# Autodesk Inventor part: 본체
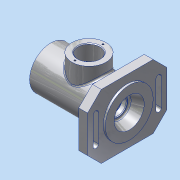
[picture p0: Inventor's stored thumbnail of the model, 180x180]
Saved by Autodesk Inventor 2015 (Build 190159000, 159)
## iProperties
Created: 2017-10
Part Number: 본체
Material: 알루미늄 6061
Document SubType Name: Modeling
Designer: Administrator
Density: 2.7 g/cm^3
Appearance: 알루미늄 - 평지
Mass: 781.743 g
Surface Area: 663.75 cm^2
Volume: 289.534 cm^3
Author: Administrator
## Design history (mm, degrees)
sketch "스케치1"
  geometry: C1 r 31 at (0, 0); 1 further point
  constraints: 1 centre point, 1 coincident
  dimensions: "d1" = 62 diameter of C1
extrude "돌출1" new body sketch "스케치1" stored distance "d2" = 99; taper "d3" = 0 deg
sketch "스케치2"
  geometry: L1 (-58, 47)-(58, 47); L2 (58, 47)-(58, -47); L3 (58, -47)-(-58, -47); L4 (-58, -47)-(-58, 47); 3 further points
  constraints: 8 end point, 2 midpoint, 2 parallel, 1 horizontal, 1 horizontal alignment, 1 perpendicular, 1 vertical alignment
  dimensions: "d4" = 116 distance between parallel lines of L2 L4; "d5" = 94 distance between parallel lines of L3 L1
extrude "돌출2" join sketch "스케치2" distance "d6" = 13; taper "d7" = 0 deg
chamfer "모따기1" distance "d8" = 20; stored, may be unused: second distance "d9" = 2, angle "d10" = 45 deg
sketch "스케치3"
  geometry: L1 (-46, 20)-(-46, -20); L2 (-50, 20)-(-50, -20); L3 (-42, -20)-(-42, 20); L4 (46, 20)-(46, -20); L5 (42, 20)-(42, -20); L6 (50, -20)-(50, 20); A1 r 4 centre (-46, 20) between (-42, 20) and (-50, 20); A2 r 4 centre (-46, -20) between (-50, -20) and (-42, -20); A3 r 4 centre (46, 20) between (50, 20) and (42, 20); A4 r 4 centre (46, -20) between (42, -20) and (50, -20); 3 further points
  constraints: 16 end point, 8 point on circle, 8 tangent, 4 centre point, 3 parallel, 2 horizontal alignment, 2 midpoint, 1 vertical
  dimensions: "d11" = 40 distance of L1.end L1.start; "d12" = 4 radius of A1; "d13" = 46 horizontal distance of point (0, 0) L1.end; "d14" = 4 radius of A3; "d15" = 92 distance of L4.end L1.end; "d16" = 40 distance of L4.end L4.start
extrude "돌출3" cut sketch "스케치3" stored distance "d17" = 13; taper "d18" = 0 deg
sketch "스케치4"
  geometry: C1 r 35 at (0, 0); 1 further point
  constraints: 1 centre point, 1 coincident
  dimensions: "d19" = 70 diameter of C1
extrude "돌출4" join sketch "스케치4" distance "d20" = 3; taper "d21" = 0 deg
sketch "스케치5"
  geometry: L1 (31, 49.5)-(-31, 49.5) reference; L2 (0, 49.5)-(0, -65.634); L3 (0, 49.5)-(21, 49.5); L4 (21, 49.5)-(21, 40.5); L5 (21, 40.5)-(24, 40.5); L6 (24, 40.5)-(24, 37.5); L7 (24, 37.5)-(21, 37.5); L8 (21, 37.5)-(21, 30.458); L9 (21, 30.458)-(17.5, 30.458); L10 (17.5, 30.458)-(17.5, 27.208); L11 (17.5, 27.208)-(18.5, 27.208); L12 (18.5, 27.208)-(18.5, 25.458); L13 (18.5, 25.458)-(17.5, 25.458); L14 (17.5, 25.458)-(17.5, 14.458); L15 (17.5, 14.458)-(0, 14.458); 1 further point
  constraints: 28 end point, 7 perpendicular, 4 vertical, 2 horizontal, 2 point on line, 1 midpoint
  dimensions: "d22" = 42 diameter of L4 L2; "d23" = 9 distance of L3.end L4.end; "d24" = 3 distance of L5.end L6.end; "d25" = 48 diameter of L6 L2; "d26" = 42 diameter of L8 L2; "d27" = 35 diameter of L10 L2; "d28" = 3.25 distance of L9.end L10.end; "d29" = 37 diameter of L12 L2; "d30" = 1.75 distance of L11.end L12.end; "d31" = 35 diameter of L14 L2; "d32" = 19.04189 distance between parallel lines of L9 L3; "d33" = 11 distance of L13.end L14.end
revolve "회전1" sketch "스케치5" stored, may be unused: angle "d34" = 90 deg
sketch "스케치6"
  geometry: L1 (0, 14.458)-(0, -65.5); L2 (0, 14.458)-(26, 14.458); L3 (17.5, 14.458)-(-17.5, 14.458) reference; L4 (26, 14.458)-(26, -23.542); L5 (26, -23.542)-(18.5, -23.542); L6 (18.5, -23.542)-(18.5, -34.542); L7 (18.5, -34.542)-(16.5, -34.542); L8 (16.5, -34.542)-(16.5, -39.542); L9 (16.5, -39.542)-(10, -39.542); L10 (10, -39.542)-(10, -42.242); L11 (10, -42.242)-(12.5, -42.242); L12 (12.5, -42.242)-(12.5, -49.542); L13 (12.5, -49.542)-(16, -49.5); L14 (-31, -49.5)-(31, -49.5) reference; L15 (16, -49.5)-(22, -65.5); L16 (-35, -65.5)-(35, -65.5) reference; L17 (22, -65.5)-(0, -65.5); 1 further point
  constraints: 28 end point, 9 perpendicular, 3 point on line, 2 collinear, 1 midpoint, 1 vertical
  dimensions: "d35" = 52 diameter of L4 L1; "d36" = 38 distance of L2.end L4.end; "d37" = 37 diameter of L6 L1; "d38" = 11 distance of L5.end L6.end; "d39" = 33 diameter of L8 L1; "d40" = 5 distance of L7.end L8.end; "d41" = 20 diameter of L10 L1; "d42" = 2.7 distance of L9.end L10.end; "d43" = 25 diameter of L12 L1; "d44" = 7.3 distance of L11.end L12.end; "d45" = 32 diameter of L13.end L1; "d46" = 44 diameter of L15.end L1
revolve "회전2" sketch "스케치6" stored, may be unused: angle "d47" = 90 deg
sketch "스케치7"
  geometry: L1 (7, -99)-(69, -99) reference; C1 r 25 at (38, -43); 2 further points
  constraints: 1 centre point, 1 midpoint, 1 vertical alignment
  dimensions: "d48" = 56 distance from line of L1 C1.centre; "d49" = 50 diameter of C1
extrude "돌출5" join sketch "스케치7" stored distance "d50" = 3; taper "d51" = 0 deg
sketch "스케치8"
  geometry: C1 r 25 at (0, 0) reference; 1 further point
hole "구멍1" sketch "스케치8" at (0, 0) diameter "d52" = 32; stored, may be unused: countersink angle "d56" = 90 deg, drill point angle "d58" = 118 deg; dims "d53" = 6, "d54" = 4, "d55" = 2, "d57" = 8
sketch "스케치9"
  geometry: C1 r 16 at (0, 0) reference; A1 r 20.5 centre (0, 0) between (-20.5, 0) and (20.5, 0); 1 further point
  constraints: 2 horizontal alignment, 2 point on circle, 1 centre point, 1 coincident
  dimensions: "d59" = 41 diameter of A1
hole "구멍2" sketch "스케치9" at (-20.5, 0), (20.5, 0) diameter "d60" = 2.459; stored, may be unused: countersink angle "d64" = 90 deg, drill point angle "d66" = 118 deg; dims "d61" = 6, "d62" = 4, "d63" = 2, "d65" = 8
chamfer "모따기2" distance "d67" = 1; stored, may be unused: second distance "d68" = 2, angle "d69" = 45 deg
feature "스레드1" dims "d70" = 10, "d71" = 0
fillet "모깎기1" dims "d76" = 3
fillet "모깎기2" dims "d77" = 0.3
chamfer "모따기3" distance "d78" = 0.7; stored, may be unused: second distance "d79" = 2, angle "d80" = 60 deg
fillet "모깎기3" dims "d81" = 3
chamfer "모따기4" distance "d82" = 1; stored, may be unused: second distance "d83" = 2, angle "d84" = 60 deg
node "솔리드1"
